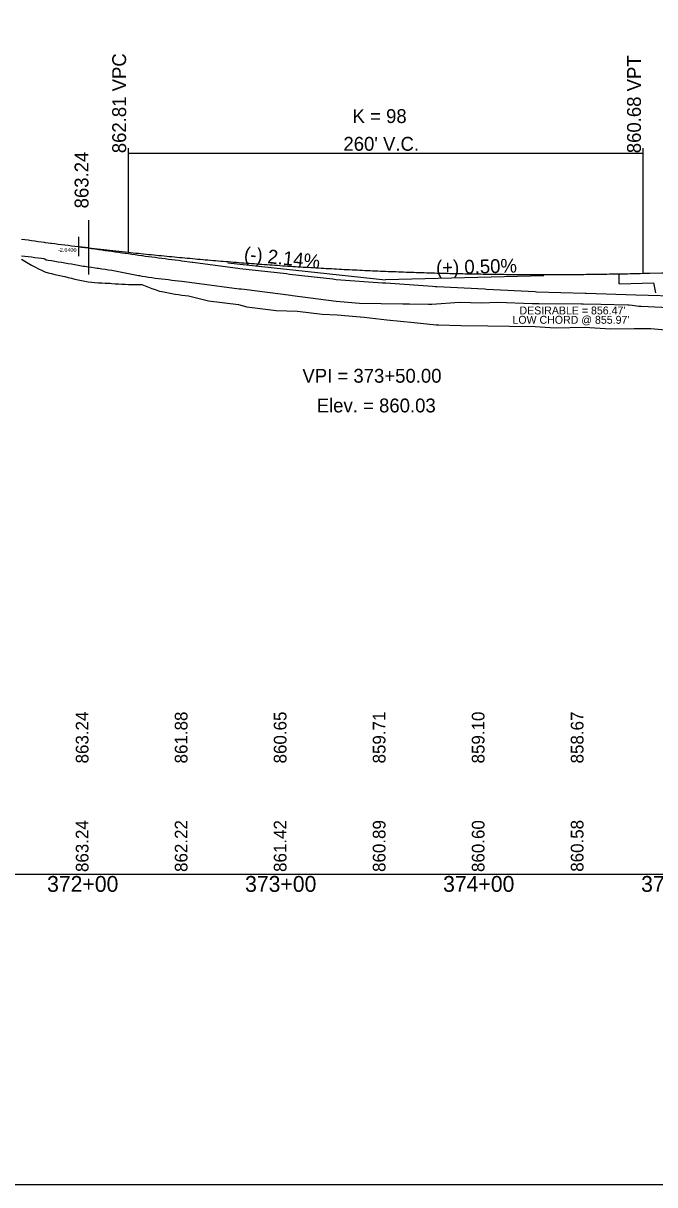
# Model space of a CAD drawing. Extents: x 1459978 to 1464152, y 1125650 to 1128602.
# Drawn here: x 1461621 to 1461940, y 1127502 to 1128089 of the extents above; entities that cross this region are included whole.
import ezdxf

# ---------------------------------------------------------------- set-up
doc = ezdxf.new("R2010")
doc.units = 0
for name, color, linetype in [('BR_CONCRETE', 7, 'Continuous'), ('BR_EXIST_GROUND_LT', 7, 'Continuous'), ('BR_EXIST_GROUND_RT', 7, 'Continuous'), ('BR_USER NOTES', 7, 'Continuous'), ('RD_DDB_GradeTX', 7, 'Continuous'), ('RD_DDB_Profile_EX', 7, 'Continuous'), ('RD_DDB_Profile_Lbl', 7, 'Continuous'), ('RD_DDB_Profile_PR', 7, 'Continuous'), ('RD_DDB_StaTX', 7, 'Continuous'), ('RD_DDB_StripGrade', 7, 'Continuous'), ('RD_DDB_VCLbl', 7, 'Continuous'), ('RD_GPK_Profile_Cell', 7, 'Continuous'), ('RD_SHT_ShtClip', 7, 'Continuous')]:
    doc.layers.add(name, color=color, linetype=linetype)

msp = doc.modelspace()

# ---------------------------------------------------------------- linework, layer by layer
at = {"layer": 'BR_CONCRETE'}
for p, q in [((1461921.69, 1127962.22), (1462111.69, 1127966.97)), ((1461921.69, 1127957.22), (1461921.69, 1127962.22)), ((1461921.69, 1127957.22), (1461939.19, 1127957.66)), ((1461940.19, 1127952.64), (1461939.19, 1127957.66))]:
    msp.add_line(p, q, dxfattribs=at)
at = {"layer": 'BR_EXIST_GROUND_LT'}
msp.add_lwpolyline([(1461619.83, 1127971.37), (1461621.52, 1127971.17), (1461623.2, 1127970.97), (1461624.89, 1127970.77), (1461626.58, 1127970.58), (1461628.27, 1127970.39), (1461629.96, 1127970.2), (1461631.06, 1127970.08), (1461631.65, 1127969.77), (1461632.38, 1127969.39), (1461633.34, 1127969.23), (1461635.03, 1127968.94), (1461636.72, 1127968.66), (1461638.4, 1127968.37), (1461640.09, 1127968.09), (1461641.78, 1127967.8), (1461643.47, 1127967.51), (1461645.16, 1127967.23), (1461646.85, 1127966.94), (1461648.54, 1127966.65), (1461650.23, 1127966.36), (1461651.26, 1127966.19), (1461651.92, 1127966.1), (1461653.6, 1127965.85), (1461655.29, 1127965.6), (1461657.15, 1127965.32), (1461658.07, 1127965.2), (1461658.8, 1127965.11), (1461660.36, 1127964.86), (1461662.05, 1127964.59), (1461663.74, 1127964.31), (1461665.43, 1127964.03), (1461667.12, 1127963.73), (1461668.8, 1127963.43), (1461670.49, 1127963.12), (1461672.18, 1127962.8), (1461673.87, 1127962.47), (1461675.56, 1127962.14), (1461677.25, 1127961.8), (1461678.94, 1127961.45), (1461679.45, 1127961.34), (1461680.63, 1127961.13), (1461682.32, 1127960.83), (1461684, 1127960.56), (1461685.69, 1127960.35), (1461687.38, 1127960.15), (1461689.07, 1127959.94), (1461690.76, 1127959.73), (1461692.45, 1127959.52), (1461694.14, 1127959.32), (1461695.83, 1127959.11), (1461697.52, 1127958.9), (1461699.2, 1127958.69), (1461700.89, 1127958.49), (1461709.71, 1127957.34), (1461729.86, 1127954.71), (1461730.87, 1127954.65), (1461732.25, 1127954.52), (1461755.81, 1127951.45), (1461756.75, 1127951.37), (1461778.84, 1127948.44), (1461780.88, 1127948.26), (1461790.55, 1127947.38), (1461812.45, 1127947.13), (1461815.88, 1127947.08), (1461825.41, 1127946.97), (1461827.1, 1127946.95), (1461841.08, 1127947.9), (1461852.24, 1127947.61), (1461860.39, 1127947.93), (1461877.71, 1127947.26), (1461881.2, 1127947.31), (1461902.76, 1127947.11), (1461903.6, 1127947.11), (1461912.4, 1127947.02), (1461926.1, 1127946.66), (1461926.8, 1127946.64), (1461928.26, 1127946.41), (1461931.69, 1127945.86), (1461932.79, 1127945.88), (1461953.77, 1127944.88)], dxfattribs=at)
at = {"layer": 'BR_EXIST_GROUND_RT'}
msp.add_lwpolyline([(1461619.83, 1127969.62), (1461621.52, 1127968.62), (1461623.2, 1127967.65), (1461624.89, 1127966.69), (1461626.58, 1127965.76), (1461628.45, 1127964.76), (1461630, 1127964.12), (1461631.65, 1127963.28), (1461633.34, 1127962.84), (1461635.03, 1127962.41), (1461636.72, 1127962), (1461638.4, 1127961.62), (1461640.09, 1127961.26), (1461640.66, 1127961.14), (1461641.78, 1127960.85), (1461643.47, 1127960.42), (1461645.16, 1127960.01), (1461646.85, 1127959.63), (1461648.54, 1127959.27), (1461650.23, 1127958.92), (1461651.92, 1127958.6), (1461653.6, 1127958.3), (1461655.31, 1127958.02), (1461656.98, 1127957.87), (1461658.67, 1127957.75), (1461660.36, 1127957.65), (1461662.05, 1127957.56), (1461663.74, 1127957.5), (1461664.68, 1127957.48), (1461665.43, 1127957.41), (1461667.12, 1127957.27), (1461668.8, 1127957.15), (1461670.49, 1127957.05), (1461672.18, 1127956.98), (1461673.87, 1127956.92), (1461675.56, 1127956.88), (1461677.25, 1127956.86), (1461679.01, 1127956.86), (1461679.54, 1127956.91), (1461680.63, 1127956.85), (1461682.32, 1127956.19), (1461684, 1127955.54), (1461685.69, 1127954.92), (1461687.38, 1127954.32), (1461689.07, 1127953.74), (1461689.56, 1127953.57), (1461690.76, 1127953.31), (1461692.45, 1127952.96), (1461694.14, 1127952.63), (1461695.83, 1127952.32), (1461697.52, 1127952.03), (1461699.2, 1127951.77), (1461700.89, 1127951.53), (1461704.23, 1127951.09), (1461714.24, 1127948.65), (1461729.4, 1127946.72), (1461733.72, 1127945.65), (1461748.4, 1127943.77), (1461759.32, 1127943.36), (1461771.74, 1127941.82), (1461779.34, 1127941.61), (1461792.92, 1127940.29), (1461804.34, 1127939.06), (1461818.17, 1127937.73), (1461829.29, 1127936.53), (1461830.42, 1127936.42), (1461841.74, 1127936.14), (1461855.46, 1127936.02), (1461866.24, 1127935.75), (1461879.31, 1127935.64), (1461889.43, 1127934.96), (1461904.27, 1127935.35), (1461917.29, 1127934.48), (1461929.23, 1127934.61), (1461937.73, 1127934.7), (1461954.37, 1127933.18)], dxfattribs=at)
at = {"layer": 'BR_USER NOTES'}
for p, q in [((1461653.69, 1127989.38), (1461653.69, 1127961.89)), ((1461648.69, 1127980.96), (1461648.69, 1127971.13)), ((1461653.69, 1127975.32), (1461648.69, 1127975.98))]:
    msp.add_line(p, q, dxfattribs=at)
at = {"layer": 'RD_DDB_GradeTX'}
for p in [(1461724.15, 1127967.79), (1461883.67, 1127961.27)]:
    msp.add_line(p, (1461803.69, 1127959.27), dxfattribs=at)
at = {"layer": 'RD_DDB_Profile_EX'}
msp.add_lwpolyline([(1461619.83, 1127979.8), (1461621.52, 1127979.57), (1461623.2, 1127979.35), (1461624.89, 1127979.12), (1461626.58, 1127978.89), (1461628.27, 1127978.65), (1461629.96, 1127978.42), (1461631.27, 1127978.24), (1461631.87, 1127978.15), (1461633.34, 1127977.94), (1461634.51, 1127977.78), (1461635.03, 1127977.72), (1461636.72, 1127977.51), (1461638.4, 1127977.3), (1461640.09, 1127977.09), (1461641.78, 1127976.87), (1461643.47, 1127976.66), (1461645.16, 1127976.44), (1461646.85, 1127976.22), (1461648.54, 1127976), (1461650.23, 1127975.78), (1461651.92, 1127975.56), (1461653.6, 1127975.34), (1461655.29, 1127975.11), (1461656.98, 1127974.88), (1461658.67, 1127974.62), (1461660.36, 1127974.35), (1461662.05, 1127974.12), (1461663.74, 1127973.89), (1461665.43, 1127973.66), (1461667.12, 1127973.43), (1461668.8, 1127973.19), (1461670.49, 1127972.95), (1461672.18, 1127972.72), (1461673.87, 1127972.48), (1461675.56, 1127972.24), (1461677.25, 1127972), (1461678.94, 1127971.75), (1461680.63, 1127971.51), (1461680.99, 1127971.46), (1461682.32, 1127971.26), (1461684, 1127971.05), (1461685.69, 1127970.83), (1461687.38, 1127970.62), (1461689.07, 1127970.4), (1461690.76, 1127970.18), (1461692.45, 1127969.97), (1461694.14, 1127969.75), (1461695.83, 1127969.53), (1461697.52, 1127969.31), (1461699.2, 1127969.09), (1461700.89, 1127968.87), (1461706.01, 1127968.21), (1461706.46, 1127968.14), (1461712.62, 1127967.35), (1461729.16, 1127965.12), (1461730.15, 1127965.01), (1461753.64, 1127962.38), (1461755.16, 1127962.14), (1461777.03, 1127959.67), (1461778.85, 1127959.38), (1461802.17, 1127957.7), (1461803.84, 1127957.68), (1461827.51, 1127955.96), (1461828.83, 1127955.94), (1461829.68, 1127955.88), (1461853.79, 1127954.62), (1461854.67, 1127954.57), (1461879.22, 1127953.28), (1461879.93, 1127953.24), (1461904.62, 1127952.47), (1461905.04, 1127952.45), (1461930.08, 1127951.68), (1461954.92, 1127950.9)], dxfattribs=at)
at = {"layer": 'RD_DDB_Profile_PR'}
for p, q in [((1461653.69, 1127975.32), (1461673.69, 1127973.18)), ((1461933.69, 1127962.52), (1462128.69, 1127967.4))]:
    msp.add_line(p, q, dxfattribs=at)
msp.add_spline([(1461673.69, 1127973.18), (1461678.89, 1127972.63), (1461684.09, 1127972.1), (1461689.29, 1127971.58), (1461694.49, 1127971.07), (1461699.69, 1127970.57), (1461704.89, 1127970.09), (1461710.09, 1127969.63), (1461715.29, 1127969.17), (1461720.49, 1127968.73), (1461725.69, 1127968.31), (1461730.89, 1127967.89), (1461736.09, 1127967.5), (1461741.29, 1127967.11), (1461746.49, 1127966.74), (1461751.69, 1127966.38), (1461756.89, 1127966.04), (1461762.09, 1127965.71), (1461767.29, 1127965.39), (1461772.49, 1127965.09), (1461777.69, 1127964.8), (1461782.89, 1127964.53), (1461788.09, 1127964.27), (1461793.29, 1127964.02), (1461798.49, 1127963.78), (1461803.69, 1127963.56), (1461808.89, 1127963.36), (1461814.09, 1127963.16), (1461819.29, 1127962.99), (1461824.49, 1127962.82), (1461829.69, 1127962.67), (1461834.89, 1127962.53), (1461840.09, 1127962.41), (1461845.29, 1127962.3), (1461850.49, 1127962.2), (1461855.69, 1127962.12), (1461860.89, 1127962.05), (1461866.09, 1127961.99), (1461871.29, 1127961.95), (1461876.49, 1127961.92), (1461881.69, 1127961.91), (1461886.89, 1127961.91), (1461892.09, 1127961.92), (1461897.29, 1127961.95), (1461902.49, 1127961.99), (1461907.69, 1127962.05), (1461912.89, 1127962.11), (1461918.09, 1127962.2), (1461923.29, 1127962.29), (1461928.49, 1127962.4), (1461933.69, 1127962.52)], degree=3, dxfattribs=at)
at = {"layer": 'RD_DDB_VCLbl'}
for p, q in [((1461673.69, 1128025.68), (1461673.69, 1127973.18)), ((1461673.69, 1128023.18), (1461933.69, 1128023.18)), ((1461933.69, 1128025.68), (1461933.69, 1127962.52))]:
    msp.add_line(p, q, dxfattribs=at)
at = {"layer": 'RD_GPK_Profile_Cell'}
msp.add_line((1460062.18, 1127659.12), (1464151.92, 1127659.12), dxfattribs=at)
at = {"layer": 'RD_SHT_ShtClip'}
msp.add_lwpolyline([(1461075.85, 1128602.16), (1462875.85, 1128602.16), (1462875.85, 1127502.16), (1461075.85, 1127502.16)], close=True, dxfattribs=at)

# ---------------------------------------------------------------- texts
at = {"layer": 'BR_USER NOTES'}
for s, height, p in [('-2.6400', 2, (1461638.28, 1127973.35)), ("DESIRABLE = 856.47'", 4, (1461871.36, 1127941.75)), ("LOW CHORD @ 855.97'", 4, (1461867.81, 1127937.04))]:
    msp.add_text(s, height=height, dxfattribs=at).set_placement(p)
at = {"layer": 'RD_DDB_GradeTX'}
for s, rotation, p in [('(-) 2.14%', 353.89259, (1461732, 1127968.96)), ('(+) 0.50%', 1.4321, (1461829.31, 1127961.91))]:
    msp.add_text(s, height=7, rotation=rotation, dxfattribs=at).set_placement(p)
at = {"layer": 'RD_DDB_Profile_Lbl'}
msp.add_text('863.24', height=7, rotation=90, dxfattribs=at).set_placement((1461653.69, 1127995.32))
for s, p in [('VPI = 373+50.00', (1461761.73, 1127907.27)), ('Elev. = 860.03', (1461768.96, 1127892.27))]:
    msp.add_text(s, height=7, dxfattribs=at).set_placement(p)
at = {"layer": 'RD_DDB_StaTX'}
for s, p in [('372+00', (1461632.79, 1127650.12)), ('373+00', (1461732.79, 1127650.12)), ('374+00', (1461832.79, 1127650.12)), ('375+00', (1461932.79, 1127650.12))]:
    msp.add_text(s, height=8, dxfattribs=at).set_placement(p)
at = {"layer": 'RD_DDB_StripGrade'}
for s, height, p in [('862.81 VPC', 7, (1461672.69, 1128023.18)), ('860.68 VPT', 7, (1461932.69, 1128023.18)), ('863.24', 6.4, (1461653.69, 1127714.97)), ('861.88', 6.4, (1461703.69, 1127714.97)), ('860.65', 6.4, (1461753.69, 1127714.97)), ('859.71', 6.4, (1461803.69, 1127714.97)), ('859.10', 6.4, (1461853.69, 1127714.97)), ('858.67', 6.4, (1461903.69, 1127714.97)), ('863.24', 6.4, (1461653.69, 1127660.12)), ('862.22', 6.4, (1461703.69, 1127660.17)), ('861.42', 6.4, (1461753.69, 1127660.17)), ('860.89', 6.4, (1461803.69, 1127660.17)), ('860.60', 6.4, (1461853.69, 1127660.13)), ('860.58', 6.4, (1461903.69, 1127660.26))]:
    msp.add_text(s, height=height, rotation=90, dxfattribs=at).set_placement(p)
at = {"layer": 'RD_DDB_VCLbl'}
for s, p in [('K = 98', (1461787.07, 1128038.43)), ("260' V.C.", (1461782.44, 1128024.43))]:
    msp.add_text(s, height=7, dxfattribs=at).set_placement(p)

doc.saveas('drawing.dxf')
